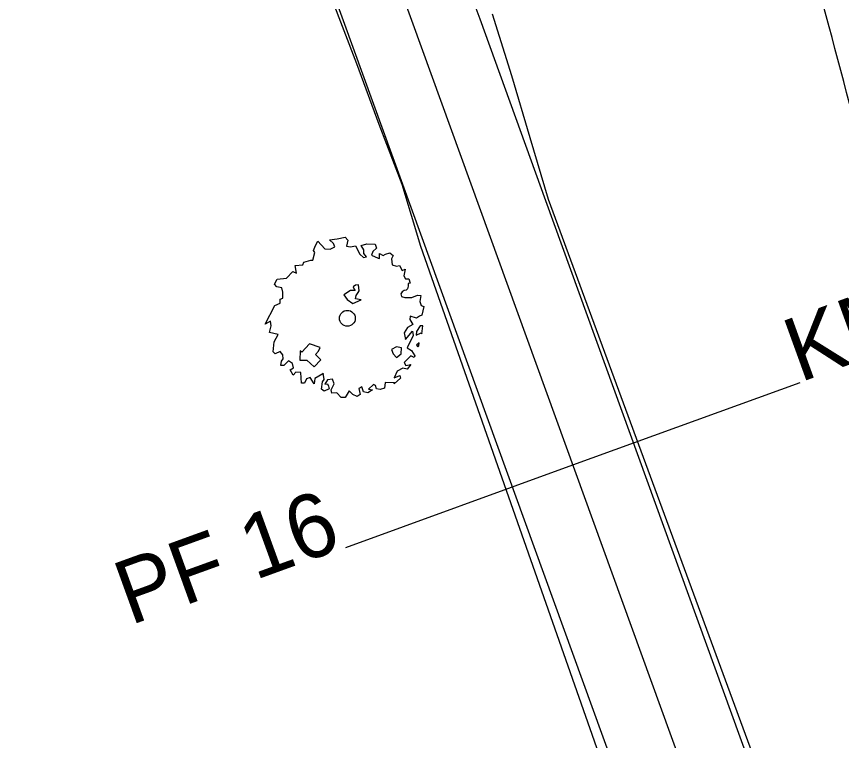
# Model space of a CAD drawing. Extents: x -475575 to -473225, y -1116053 to -1114104.
# Drawn here: x -474248.06 to -474222.45, y -1114975.21 to -1114952.74 of the extents above; entities that cross this region are included whole.
import ezdxf

# ---------------------------------------------------------------- set-up
doc = ezdxf.new("R2010")
doc.units = 0
for name, color, linetype in [('CESTN___P____KOP_N__VRH__Construction_', 7, 'Continuous'), ('IP', 7, 'Continuous'), ('POLYGONY_SITUACE_PF', 7, 'Continuous'), ('POLYGONY_SITUACE_PF_POPISY', 7, 'Continuous'), ('POLYGONY_SITUACE_PO', 7, 'Continuous'), ('Vrstevnice_vedlejsi', 7, 'Continuous')]:
    doc.layers.add(name, color=color, linetype=linetype)

msp = doc.modelspace()

# ---------------------------------------------------------------- linework, layer by layer
at = {"layer": 'CESTN___P____KOP_N__VRH__Construction_'}
for p, q in [((-474243.227, -1114926.494), (-474233.682, -1114952.817)), ((-474246.987, -1114927.857), (-474210.542, -1115028.369)), ((-474247.492, -1114928.04), (-474237.508, -1114954.204)), ((-474232.688, -1114954.584), (-474233.282, -1114952.672)), ((-474233.682, -1114952.817), (-474231.637, -1114958.457)), ((-474237.508, -1114954.204), (-474236.814, -1114956.08)), ((-474232.117, -1114956.504), (-474232.688, -1114954.584)), ((-474236.814, -1114956.08), (-474236.095, -1114957.947)), ((-474231.546, -1114958.425), (-474232.117, -1114956.504)), ((-474236.095, -1114957.947), (-474235.524, -1114959.867)), ((-474231.637, -1114958.457), (-474205.729, -1115029.905)), ((-474205.264, -1115029.737), (-474231.546, -1114958.425)), ((-474235.524, -1114959.867), (-474211.725, -1115027.539))]:
    msp.add_line(p, q, dxfattribs=at)
at = {"layer": 'IP'}
for points in [[(-474235.82, -1114963.539), (-474235.934, -1114963.687), (-474236.063, -1114963.653), (-474236.239, -1114963.744), (-474236.335, -1114963.953), (-474236.164, -1114963.887), (-474236.14, -1114963.966), (-474236.334, -1114964.145), (-474236.322, -1114964.11), (-474236.618, -1114964.096), (-474236.639, -1114964.278), (-474236.768, -1114964.317), (-474236.886, -1114964.294), (-474236.911, -1114964.19), (-474236.981, -1114964.161), (-474237.134, -1114964.312), (-474237.01, -1114964.333), (-474237.153, -1114964.426), (-474237.287, -1114964.389), (-474237.337, -1114964.236), (-474237.431, -1114964.283), (-474237.389, -1114964.476), (-474237.483, -1114964.531), (-474237.619, -1114964.472), (-474237.732, -1114964.355), (-474237.861, -1114964.567), (-474237.983, -1114964.563), (-474238.113, -1114964.421), (-474238.268, -1114964.435), (-474238.292, -1114964.328), (-474238.2, -1114964.137), (-474238.249, -1114963.992), (-474238.408, -1114964.017), (-474238.492, -1114964.154), (-474238.408, -1114964.143), (-474238.371, -1114964.21), (-474238.352, -1114964.3), (-474238.505, -1114964.373), (-474238.594, -1114964.308), (-474238.564, -1114964.083), (-474238.514, -1114964.005), (-474238.541, -1114963.814), (-474238.548, -1114963.834), (-474238.797, -1114963.974), (-474238.819, -1114964.138), (-474238.941, -1114963.949), (-474239.062, -1114963.987), (-474239.118, -1114964.12), (-474239.216, -1114964.117), (-474239.232, -1114963.792), (-474239.392, -1114963.785), (-474239.469, -1114963.875), (-474239.563, -1114963.712), (-474239.462, -1114963.644), (-474239.494, -1114963.507), (-474239.617, -1114963.425), (-474239.765, -1114963.568), (-474239.852, -1114963.569), (-474239.832, -1114963.434), (-474239.786, -1114963.364), (-474239.791, -1114963.243), (-474239.874, -1114963.136), (-474240.033, -1114963.212), (-474240.094, -1114963.147), (-474240.061, -1114962.837), (-474239.939, -1114962.608), (-474240.209, -1114962.548), (-474240.154, -1114962.34), (-474240.171, -1114962.193), (-474240.339, -1114962.286), (-474240.04, -1114961.709), (-474239.878, -1114961.64), (-474239.872, -1114961.511), (-474239.797, -1114961.483), (-474239.793, -1114961.302), (-474239.82, -1114961.165), (-474239.977, -1114961.136), (-474240.047, -1114961.049), (-474239.967, -1114960.894), (-474239.683, -1114960.861), (-474239.481, -1114960.654), (-474239.37, -1114960.713), (-474239.414, -1114960.469), (-474239.169, -1114960.453), (-474239.142, -1114960.364), (-474238.918, -1114960.301), (-474238.865, -1114960.302), (-474238.802, -1114960.071), (-474238.84, -1114960.004), (-474238.782, -1114959.846), (-474238.702, -1114959.72), (-474238.492, -1114959.956), (-474238.325, -1114959.963), (-474238.182, -1114959.894), (-474238.217, -1114959.786), (-474238.345, -1114959.679), (-474238.106, -1114959.648), (-474237.859, -1114959.589), (-474237.772, -1114959.686), (-474237.813, -1114959.875), (-474237.69, -1114959.893), (-474237.539, -1114959.861), (-474237.406, -1114960.119), (-474237.292, -1114960.217), (-474237.197, -1114960.199), (-474237.274, -1114960.102), (-474237.274, -1114959.988), (-474237.359, -1114959.852), (-474237.184, -1114959.798), (-474236.931, -1114959.813), (-474236.883, -1114959.933), (-474237.003, -1114960.036), (-474237.043, -1114960.145), (-474236.833, -1114960.247), (-474236.797, -1114960.258), (-474236.795, -1114960.103), (-474236.677, -1114960.161), (-474236.604, -1114960.117), (-474236.474, -1114960.073), (-474236.372, -1114960.163), (-474236.416, -1114960.267), (-474236.399, -1114960.445), (-474236.26, -1114960.49), (-474236.175, -1114960.472), (-474236.087, -1114960.63), (-474235.993, -1114960.589), (-474236.036, -1114960.794), (-474235.984, -1114960.886), (-474235.88, -1114960.881), (-474235.835, -1114961.016), (-474235.905, -1114961.03), (-474235.899, -1114961.112), (-474235.925, -1114961.199), (-474235.963, -1114961.233), (-474236.03, -1114961.248), (-474236.09, -1114961.291), (-474236.131, -1114961.345), (-474236.107, -1114961.428), (-474236.008, -1114961.464), (-474235.787, -1114961.465), (-474235.617, -1114961.391), (-474235.512, -1114961.4), (-474235.543, -1114961.583), (-474235.498, -1114961.713), (-474235.42, -1114961.744), (-474235.482, -1114962.016), (-474235.55, -1114962.038), (-474235.645, -1114962.1), (-474235.842, -1114962.045), (-474235.85, -1114962.144), (-474235.762, -1114962.3), (-474235.92, -1114962.397), (-474236.03, -1114962.563), (-474235.987, -1114962.766), (-474235.764, -1114962.511), (-474235.752, -1114962.647), (-474235.929, -1114963.024), (-474235.794, -1114963.106), (-474235.694, -1114963.275), (-474235.715, -1114963.32), (-474235.818, -1114963.272), (-474236.022, -1114963.48), (-474235.978, -1114963.576)], [(-474237.549, -1114961.247), (-474237.692, -1114961.247), (-474237.894, -1114961.376), (-474237.797, -1114961.527), (-474237.622, -1114961.654), (-474237.362, -1114961.532), (-474237.538, -1114961.502), (-474237.52, -1114961.399), (-474237.45, -1114961.303), (-474237.42, -1114961.261), (-474237.442, -1114961.074), (-474237.537, -1114961.085), (-474237.613, -1114961.136), (-474237.583, -1114961.208)], [(-474235.529, -1114962.341), (-474235.641, -1114962.518), (-474235.656, -1114962.633), (-474235.502, -1114962.559), (-474235.478, -1114962.591), (-474235.443, -1114962.343)], [(-474238.633, -1114963.015), (-474238.961, -1114962.901), (-474239.202, -1114963.162), (-474239.255, -1114963.113), (-474239.262, -1114963.403), (-474239.042, -1114963.408), (-474238.82, -1114963.617), (-474238.612, -1114963.395), (-474238.781, -1114963.236), (-474238.683, -1114963.132)], [(-474235.562, -1114962.866), (-474235.641, -1114962.941), (-474235.603, -1114962.99), (-474235.569, -1114962.965)], [(-474236.109, -1114963.022), (-474236.266, -1114962.995), (-474236.416, -1114963.073), (-474236.364, -1114963.211), (-474236.26, -1114963.32), (-474236.123, -1114963.207)]]:
    msp.add_lwpolyline(points, close=True, dxfattribs=at)
msp.add_circle((-474237.789, -1114962.109), 0.247, dxfattribs=at)
at = {"layer": 'POLYGONY_SITUACE_PF'}
msp.add_lwpolyline([(-474237.841, -1114969.216), (-474230.79, -1114966.66), (-474223.739, -1114964.103)], dxfattribs=at)
at = {"layer": 'POLYGONY_SITUACE_PO'}
msp.add_lwpolyline([(-474033.93, -1115484.017), (-474028.81, -1115469.55), (-474027.706, -1115465.586), (-474027.155, -1115461.509), (-474027.167, -1115457.394), (-474027.702, -1115449.947), (-474028.133, -1115446.706), (-474028.952, -1115443.542), (-474030.148, -1115440.499), (-474155.776, -1115170.193), (-474159.336, -1115162.232), (-474162.663, -1115154.172), (-474165.754, -1115146.018), (-474287.504, -1114810.25), (-474291.915, -1114795.876)], dxfattribs=at)
at = {"layer": 'Vrstevnice_vedlejsi'}
for points in [[(-474198.341, -1114669.49), (-474196.681, -1114672.256), (-474195.18, -1114674.653), (-474193.836, -1114676.681), (-474192.651, -1114678.341), (-474192.443, -1114683.526), (-474193.214, -1114692.237), (-474194.962, -1114704.473), (-474196.31, -1114712.997), (-474197.258, -1114717.807), (-474197.807, -1114718.903), (-474198.355, -1114720.033), (-474198.903, -1114721.196), (-474199.452, -1114722.393), (-474202.29, -1114724.764), (-474207.417, -1114728.309), (-474214.834, -1114733.029), (-474221.352, -1114738.648), (-474226.971, -1114745.166), (-474231.691, -1114752.583), (-474235.037, -1114757.727), (-474237.009, -1114760.598), (-474237.607, -1114761.196), (-474238.205, -1114762.022), (-474238.804, -1114763.076), (-474239.402, -1114764.358), (-474242.028, -1114769.031), (-474246.681, -1114777.093), (-474253.362, -1114788.547), (-474258.559, -1114799.152), (-474262.27, -1114808.908), (-474264.497, -1114817.816), (-474266.676, -1114825.23), (-474268.807, -1114831.15), (-474270.889, -1114835.575), (-474272.278, -1114842.188), (-474272.972, -1114850.991), (-474272.972, -1114861.981), (-474273.054, -1114870.089), (-474273.218, -1114875.314), (-474273.465, -1114877.657), (-474273.273, -1114882.608), (-474272.641, -1114890.167), (-474271.571, -1114900.334), (-474271.061, -1114908.167), (-474271.11, -1114913.667), (-474271.719, -1114916.834), (-474271.646, -1114922.058), (-474270.891, -1114929.339), (-474269.454, -1114938.678), (-474268.091, -1114946.236), (-474266.802, -1114952.012), (-474265.586, -1114956.006), (-474264.292, -1114960.893), (-474262.92, -1114966.673), (-474261.469, -1114973.346), (-474259.897, -1114980.014), (-474258.202, -1114986.679), (-474256.386, -1114993.34), (-474254.916, -1115000.31), (-474253.793, -1115007.591), (-474253.017, -1115015.182), (-474252.121, -1115021.507), (-474251.104, -1115026.568), (-474249.968, -1115030.364), (-474249.22, -1115033.873), (-474248.86, -1115037.095), (-474248.889, -1115040.031), (-474248.926, -1115042.279), (-474248.97, -1115043.838), (-474249.022, -1115044.709), (-474249.185, -1115045.346), (-474249.46, -1115045.75), (-474249.845, -1115045.92), (-474250.053, -1115046.628), (-474250.085, -1115047.873), (-474249.939, -1115049.656), (-474250.24, -1115054.341), (-474250.987, -1115061.928), (-474252.18, -1115072.418), (-474252.552, -1115080.569), (-474252.103, -1115086.383), (-474250.833, -1115089.859), (-474248.888, -1115093.001), (-474246.267, -1115095.808), (-474242.971, -1115098.281), (-474237.53, -1115101.018), (-474229.942, -1115104.018), (-474220.207, -1115107.282), (-474212.554, -1115110.016), (-474206.982, -1115112.221), (-474203.491, -1115113.895), (-474200.507, -1115114.848), (-474198.031, -1115115.078), (-474196.062, -1115114.586), (-474193.634, -1115114.914), (-474190.746, -1115116.062)], [(-474106.724, -1115139.906), (-474105.975, -1115134.747), (-474104.91, -1115130.242), (-474103.528, -1115126.392), (-474101.829, -1115123.196), (-474101.248, -1115119.409), (-474101.786, -1115115.032), (-474103.442, -1115110.065), (-474106.201, -1115105.465), (-474110.065, -1115101.234), (-474115.032, -1115097.37), (-474120.595, -1115093.294), (-474126.753, -1115089.004), (-474133.506, -1115084.502), (-474139.856, -1115081.154), (-474145.801, -1115078.961), (-474151.342, -1115077.922), (-474155.382, -1115077.318), (-474157.922, -1115077.148), (-474158.961, -1115077.413), (-474159.927, -1115077.355), (-474160.82, -1115076.975), (-474161.64, -1115076.273), (-474163.375, -1115076.297), (-474166.027, -1115077.047), (-474169.593, -1115078.523), (-474174.953, -1115080.253), (-474182.107, -1115082.237), (-474191.053, -1115084.473), (-474198.277, -1115085.36), (-474203.777, -1115084.898), (-474207.554, -1115083.087), (-474210.582, -1115078.783), (-474212.862, -1115071.987), (-474214.394, -1115062.7), (-474215.425, -1115054.98), (-474215.955, -1115048.829), (-474215.985, -1115044.245), (-474215.583, -1115041.048), (-474214.749, -1115039.236), (-474213.484, -1115038.81), (-474212.393, -1115038.422), (-474211.477, -1115038.073), (-474210.736, -1115037.762), (-474210.235, -1115036.623), (-474209.974, -1115034.657), (-474209.953, -1115031.862), (-474210.087, -1115026.769), (-474210.376, -1115019.378), (-474210.819, -1115009.689), (-474212.181, -1114998.785), (-474214.462, -1114986.667), (-474217.662, -1114973.333), (-474220.697, -1114961.225), (-474223.567, -1114950.342), (-474226.271, -1114940.683), (-474228.65, -1114933.019), (-474230.705, -1114927.35), (-474232.434, -1114923.675), (-474233.1, -1114917.916), (-474232.704, -1114910.072), (-474231.244, -1114900.144), (-474229.766, -1114892.391), (-474228.27, -1114886.811), (-474226.756, -1114883.405), (-474225.554, -1114878.524), (-474224.663, -1114872.166), (-474224.082, -1114864.332), (-474222.871, -1114857.276), (-474221.027, -1114850.999), (-474218.553, -1114845.499), (-474216.392, -1114840.557), (-474214.547, -1114836.172), (-474213.015, -1114832.344), (-474210.719, -1114828.319), (-474207.656, -1114824.099), (-474203.828, -1114819.682), (-474200.394, -1114815.041), (-474197.354, -1114810.176), (-474194.708, -1114805.088), (-474192.13, -1114800), (-474189.62, -1114794.912), (-474187.178, -1114789.824), (-474182.801, -1114780.435), (-474176.49, -1114766.746), (-474168.245, -1114748.757), (-474162.295, -1114736.021), (-474158.639, -1114728.54), (-474157.277, -1114726.312), (-474156.001, -1114724.373), (-474154.81, -1114722.723), (-474153.704, -1114721.361), (-474151.414, -1114718.384), (-474147.941, -1114713.791), (-474143.284, -1114707.582), (-474139.388, -1114701.068), (-474136.252, -1114694.249)], [(-474227.218, -1115164.851), (-474226.448, -1115162.426), (-474227.525, -1115159.571), (-474230.451, -1115156.287), (-474235.226, -1115152.573), (-474240.399, -1115148.881), (-474245.971, -1115145.211), (-474251.942, -1115141.562), (-474256.818, -1115137.139), (-474260.6, -1115131.942), (-474263.287, -1115125.971), (-474265.918, -1115121.36), (-474268.492, -1115118.11), (-474271.011, -1115116.221), (-474273.409, -1115112.993), (-474275.686, -1115108.429), (-474277.843, -1115102.526), (-474279.974, -1115096.744), (-474282.078, -1115091.082), (-474284.156, -1115085.541), (-474285.812, -1115080.883), (-474287.047, -1115077.109), (-474287.86, -1115074.218), (-474288.244, -1115068.81), (-474288.198, -1115060.885), (-474287.724, -1115050.442), (-474287.488, -1115042.595), (-474287.491, -1115037.342), (-474287.732, -1115034.684), (-474288.91, -1115029.354), (-474291.024, -1115021.351), (-474294.074, -1115010.675), (-474297.009, -1115000.754), (-474299.828, -1114991.588), (-474302.532, -1114983.176), (-474304.676, -1114975.928), (-474306.261, -1114969.843), (-474307.286, -1114964.921), (-474309.265, -1114957.199), (-474312.198, -1114946.677), (-474316.084, -1114933.354), (-474318.675, -1114924.468), (-474319.971, -1114920.02), (-474319.973, -1114920.01), (-474319.977, -1114919.992), (-474319.984, -1114919.965), (-474319.992, -1114919.931), (-474321.301, -1114916.779), (-474323.911, -1114910.509), (-474327.823, -1114901.121), (-474333.571, -1114893.897), (-474341.156, -1114888.835), (-474350.578, -1114885.936), (-474361.246, -1114883.666), (-474373.16, -1114882.025), (-474386.32, -1114881.012), (-474395.152, -1114880.336), (-474399.654, -1114879.994), (-474399.827, -1114879.989), (-474403.877, -1114879.477), (-474411.805, -1114878.46), (-474423.609, -1114876.937), (-474431.988, -1114875.62), (-474436.942, -1114874.51), (-474438.471, -1114873.607), (-474443.932, -1114869.371), (-474453.324, -1114861.802), (-474466.647, -1114850.901), (-474475.533, -1114843.63), (-474479.981, -1114839.989), (-474479.99, -1114839.978), (-474480.008, -1114839.975), (-474480.035, -1114839.978), (-474480.069, -1114839.989), (-474480.092, -1114840.008), (-474480.104, -1114840.035), (-474480.104, -1114840.069), (-474483.152, -1114844.525), (-474489.247, -1114853.403), (-474498.39, -1114866.701), (-474505.505, -1114879.646), (-474510.592, -1114892.237), (-474513.651, -1114904.473), (-474515.798, -1114912.997), (-474517.033, -1114917.807), (-474517.355, -1114918.903), (-474517.71, -1114919.879), (-474518.097, -1114920.733), (-474518.517, -1114921.467), (-474518.841, -1114922.054), (-474519.069, -1114922.494), (-474519.202, -1114922.788), (-474519.513, -1114923.611), (-474520.002, -1114924.961), (-474520.669, -1114926.839), (-474521.912, -1114930.34), (-474523.73, -1114935.464)]]:
    msp.add_spline(points, degree=3, dxfattribs=at)

# ---------------------------------------------------------------- texts
at = {"layer": 'POLYGONY_SITUACE_PF_POPISY'}
for s, p in [('KM=0.560', (-474223.751, -1114964.107)), ('PF 16', (-474244.53, -1114971.642))]:
    msp.add_text(s, height=1.9765, rotation=19.9307, dxfattribs=at).set_placement(p)

doc.saveas('drawing.dxf')
